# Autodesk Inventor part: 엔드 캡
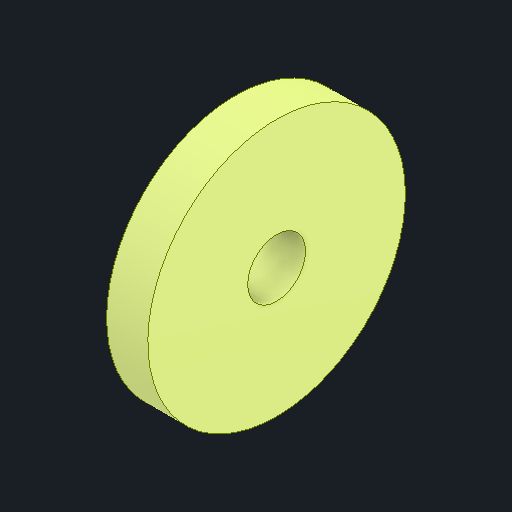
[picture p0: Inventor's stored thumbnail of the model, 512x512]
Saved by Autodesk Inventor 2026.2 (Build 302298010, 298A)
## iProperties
Created: 2026-03
Part Number: 엔드 캡
Material: 강철, 연강
Document SubType Name: Modeling
Designer: PC2-02
Density: 7.85 g/cm^3
Appearance: 기본값
Author: jhkim
Sending System: Autodesk Inventor 2026
Preprocessor: ST-DEVELOPER v20.1
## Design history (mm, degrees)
feature "솔리드1"
node "솔리드2"
